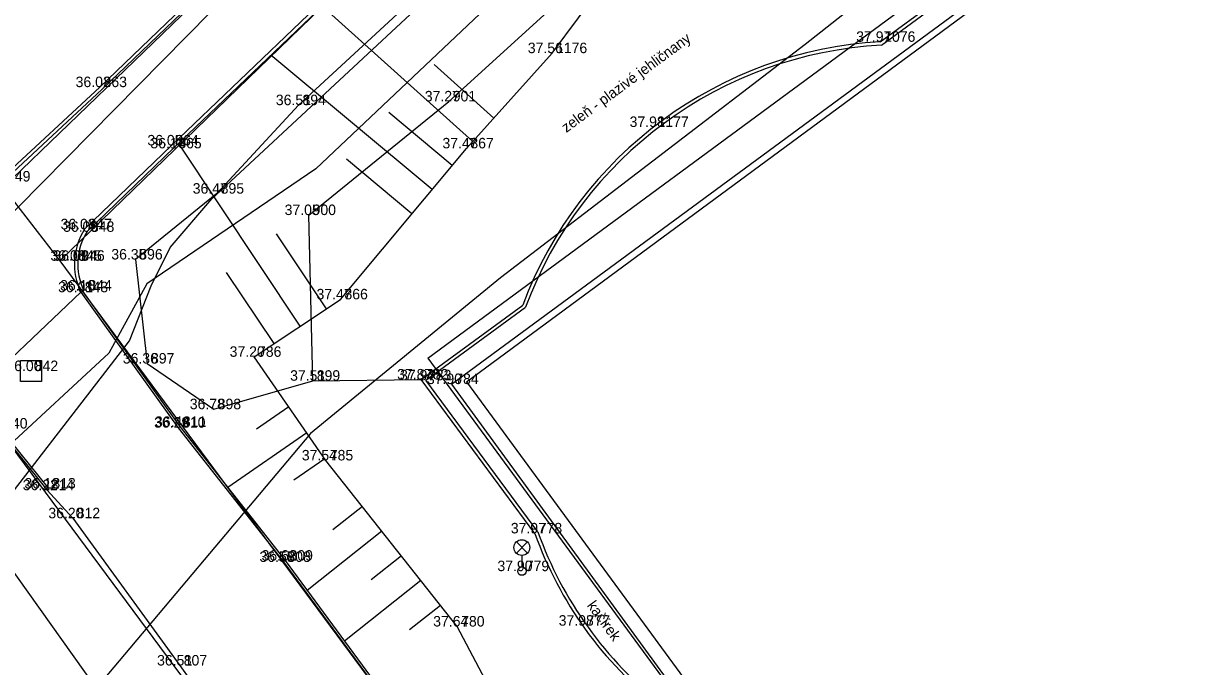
# Model space of a CAD drawing. Extents: x -609709 to -609357, y -1051535 to -1051131.
# Drawn here: x -609623.05 to -609595.44, y -1051283.31 to -1051267.96 of the extents above; entities that cross this region are included whole.
import ezdxf

# ---------------------------------------------------------------- set-up
doc = ezdxf.new("R2010")
doc.units = 0
for name, color, linetype in [('Vrstva 1', 7, 'Continuous'), ('Vrstva 10', 7, 'Continuous'), ('Vrstva 12', 7, 'Continuous'), ('Vrstva 15', 7, 'Continuous'), ('Vrstva 17', 7, 'Continuous'), ('Vrstva 2', 7, 'Continuous'), ('Vrstva 3', 7, 'Continuous'), ('Vrstva 4', 7, 'Continuous'), ('Vrstva 5', 7, 'Continuous'), ('Vrstva 6', 7, 'Continuous'), ('Vrstva 7', 7, 'Continuous'), ('Vrstva 8', 7, 'Continuous'), ('Vrstva 9', 7, 'Continuous')]:
    doc.layers.add(name, color=color, linetype=linetype)

msp = doc.modelspace()

# ---------------------------------------------------------------- linework, layer by layer
at = {"layer": 'Vrstva 1'}
for p, q in [((-609602.63, -1051268.41), (-609602.63, -1051268.41)), ((-609610.45, -1051268.68), (-609610.45, -1051268.68)), ((-609621.23, -1051269.49), (-609621.23, -1051269.49)), ((-609616.49, -1051269.92), (-609616.49, -1051269.92)), ((-609612.91, -1051269.83), (-609612.91, -1051269.83)), ((-609608.03, -1051270.44), (-609608.03, -1051270.44)), ((-609619.52, -1051270.88), (-609619.52, -1051270.88)), ((-609619.45, -1051270.95), (-609619.45, -1051270.95)), ((-609612.49, -1051270.95), (-609612.49, -1051270.95)), ((-609618.44, -1051272.03), (-609618.44, -1051272.03)), ((-609616.25, -1051272.54), (-609616.25, -1051272.54)), ((-609621.59, -1051272.88), (-609621.59, -1051272.88)), ((-609621.53, -1051272.94), (-609621.53, -1051272.94)), ((-609621.83, -1051273.63), (-609621.83, -1051273.63)), ((-609621.76, -1051273.63), (-609621.76, -1051273.63)), ((-609620.38, -1051273.6), (-609620.38, -1051273.6)), ((-609621.59, -1051274.34), (-609621.59, -1051274.34)), ((-609621.68, -1051274.38), (-609621.68, -1051274.38)), ((-609615.49, -1051274.55), (-609615.49, -1051274.55)), ((-609617.55, -1051275.92), (-609617.55, -1051275.92)), ((-609622.87, -1051276.26), (-609622.87, -1051276.26)), ((-609620.1, -1051276.08), (-609620.1, -1051276.08)), ((-609616.15, -1051276.49), (-609616.15, -1051276.49)), ((-609613.57, -1051276.46), (-609613.57, -1051276.46)), ((-609613.5, -1051276.48), (-609613.5, -1051276.48)), ((-609612.85, -1051276.57), (-609612.85, -1051276.57)), ((-609618.51, -1051277.17), (-609618.51, -1051277.17)), ((-609619.36, -1051277.61), (-609619.36, -1051277.61)), ((-609619.34, -1051277.59), (-609619.34, -1051277.59)), ((-609615.84, -1051278.39), (-609615.84, -1051278.39)), ((-609622.45, -1051279.06), (-609622.45, -1051279.06)), ((-609622.49, -1051279.1), (-609622.49, -1051279.1)), ((-609621.87, -1051279.77), (-609621.87, -1051279.77)), ((-609610.86, -1051280.13), (-609610.86, -1051280.13)), ((-609616.85, -1051280.81), (-609616.85, -1051280.81)), ((-609616.8, -1051280.78), (-609616.8, -1051280.78)), ((-609611.17, -1051281.03), (-609611.17, -1051281.03)), ((-609612.71, -1051282.35), (-609612.71, -1051282.35)), ((-609609.72, -1051282.33), (-609609.72, -1051282.33)), ((-609619.32, -1051283.28), (-609619.32, -1051283.28))]:
    msp.add_line(p, q, dxfattribs=at)
at = {"layer": 'Vrstva 10'}
for p, q in [((-609623.53, -1051271.88), (-609592.58, -1051242.01)), ((-609622.18, -1051273.63), (-609589.38, -1051241.83)), ((-609613.41, -1051275.95), (-609597.54, -1051264.25)), ((-609612.49, -1051276.52), (-609596.95, -1051265.05)), ((-609623.53, -1051271.88), (-609622.18, -1051273.63)), ((-609622.18, -1051273.63), (-609602.58, -1051300.13)), ((-609613.41, -1051275.95), (-609598.09, -1051296.84)), ((-609612.49, -1051276.52), (-609597.77, -1051296.6)), ((-609623.67, -1051277.61), (-609605.63, -1051301.94))]:
    msp.add_line(p, q, dxfattribs=at)
at = {"layer": 'Vrstva 12'}
for points in [[(-609644.336, -1051251.436), (-609604.801, -1051307.048), (-609620.698, -1051318.606), (-609619.426, -1051320.272)], [(-609598.88, -1051264.1), (-609604.42, -1051268.47), (-609611.68, -1051274.04), (-609616.21, -1051277.75), (-609621.57, -1051284.12), (-609621.25, -1051285.42), (-609619.8, -1051287.45), (-609615.97, -1051291.57), (-609612.96, -1051295.31), (-609611.54, -1051298.14), (-609609.99, -1051301.94), (-609609.26, -1051303.04), (-609608.61, -1051303.76)]]:
    msp.add_lwpolyline(points, dxfattribs=at)
at = {"layer": 'Vrstva 15'}
for points in [[(-609592.54, -1051249), (-609597.09, -1051253.54), (-609603.86, -1051260.31), (-609608.84, -1051264.59), (-609616.08, -1051271.44), (-609620.11, -1051274.18), (-609621.01, -1051275.83), (-609623.48, -1051278.12), (-609624.89, -1051278.61), (-609626.41, -1051281.76), (-609625.78, -1051282.81), (-609616.94, -1051293.56), (-609613.57, -1051297.39), (-609614.852, -1051298.693)], [(-609615.07, -1051296.33), (-609615.78, -1051295.09), (-609620.45, -1051288.93), (-609623.66, -1051284.97), (-609624.82, -1051283.57), (-609624.94, -1051283.19), (-609624.89, -1051282.73), (-609624.27, -1051280.91), (-609623.86, -1051279.98), (-609623.26, -1051279.09), (-609620.52, -1051275.54), (-609620, -1051274.23), (-609619.55, -1051273.31), (-609618.56, -1051272.15), (-609610.34, -1051264.5)]]:
    msp.add_lwpolyline(points, dxfattribs=at)
at = {"layer": 'Vrstva 17'}
msp.add_lwpolyline([(-609531.786, -1051180.515), (-609532.61, -1051181.07), (-609528.54, -1051185.58), (-609545.95, -1051201.69), (-609546.72, -1051202.27), (-609551.04, -1051206.15), (-609565.42, -1051219.63), (-609579.77, -1051233.3), (-609583.56, -1051235.84), (-609591.75, -1051241.92), (-609609.05, -1051258.52), (-609618.01, -1051267.11), (-609626.05, -1051275.26), (-609630.23, -1051279.58), (-609635.78, -1051285.7), (-609642.85, -1051291.4), (-609672.95, -1051307.23)], dxfattribs=at)
at = {"layer": 'Vrstva 4'}
for p, q in [((-609602.602, -1051268.489), (-609598.603, -1051265.555)), ((-609617.947, -1051266.442), (-609621.175, -1051269.548)), ((-609621.229, -1051269.489), (-609623.519, -1051271.62)), ((-609610.789, -1051280.092), (-609613.458, -1051276.477)), ((-609623.638, -1051277.663), (-609622.489, -1051279.091))]:
    msp.add_line(p, q, dxfattribs=at)
for points in [[(-609601.06, -1051253.08), (-609604.02, -1051255.96), (-609607.62, -1051259.41), (-609610.87, -1051262.54), (-609616.26, -1051267.77), (-609619.52, -1051270.88), (-609621.59, -1051272.88)], [(-609601.004, -1051253.137), (-609603.964, -1051256.018), (-609607.565, -1051259.468), (-609610.814, -1051262.598), (-609616.205, -1051267.828), (-609619.465, -1051270.938), (-609621.528, -1051272.931)], [(-609602.63, -1051268.41), (-609598.65, -1051265.49), (-609596.65, -1051264.02), (-609592.713, -1051261.096)], [(-609618.06, -1051266.44), (-609621.23, -1051269.49)], [(-609621.175, -1051269.548), (-609623.53, -1051271.74)], [(-609621.68, -1051274.38), (-609621.611, -1051274.339)], [(-609621.637, -1051274.354), (-609619.32, -1051277.58), (-609616.81, -1051280.78), (-609610.823, -1051288.92)], [(-609621.68, -1051274.38), (-609624.49, -1051277.05)], [(-609621.68, -1051274.38), (-609619.36, -1051277.61), (-609616.85, -1051280.81), (-609610.863, -1051288.949)], [(-609613.57, -1051276.46), (-609611.149, -1051274.688)], [(-609613.458, -1051276.477), (-609611.083, -1051274.738)], [(-609610.86, -1051280.13), (-609613.57, -1051276.46)], [(-609623.6, -1051277.63), (-609622.45, -1051279.06)], [(-609622.489, -1051279.091), (-609622.45, -1051279.06)], [(-609622.489, -1051279.091), (-609621.87, -1051279.77), (-609619.32, -1051283.28), (-609616.512, -1051287.217)]]:
    msp.add_lwpolyline(points, dxfattribs=at)
for centre, radius, start, end in [((-609602.075, -1051278.082), 9.688, 93.2811, 159.4889), ((-609602.075, -1051278.082), 9.608, 93.1402, 159.6312), ((-609620.285, -1051273.711), 1.547, 147.5118, 205.621), ((-609620.285, -1051273.711), 1.467, 147.8766, 205.3494), ((-609602.176, -1051277.026), 9.222, 199.6719, 231.8723), ((-609602.176, -1051277.026), 9.142, 199.5981, 231.9379)]:
    msp.add_arc(centre, radius, start, end, dxfattribs=at)
at = {"layer": 'Vrstva 5'}
for p, q in [((-609611.302, -1051280.6), (-609611.037, -1051280.335)), ((-609611.302, -1051280.335), (-609611.037, -1051280.6)), ((-609611.17, -1051280.655), (-609611.17, -1051280.93))]:
    msp.add_line(p, q, dxfattribs=at)
msp.add_lwpolyline([(-609623.12, -1051276.01), (-609622.62, -1051276.01), (-609622.62, -1051276.51), (-609623.12, -1051276.51)], close=True, dxfattribs=at)
for centre, radius in [((-609611.17, -1051280.468), 0.188), ((-609611.17, -1051281.03), 0.1)]:
    msp.add_circle(centre, radius, dxfattribs=at)
at = {"layer": 'Vrstva 6'}
msp.add_lwpolyline([(-609610.31, -1051288.53), (-609610.4, -1051286.73), (-609612.71, -1051282.35), (-609615.84, -1051278.39), (-609617.55, -1051275.92), (-609615.49, -1051274.55), (-609612.49, -1051270.95), (-609610.45, -1051268.68), (-609607.94, -1051265.3), (-609606.28, -1051264.06), (-609602.59, -1051259.95), (-609593.93, -1051248.07), (-609590.64, -1051244.54), (-609589.23, -1051241.892)], dxfattribs=at)
at = {"layer": 'Vrstva 7'}
for points in [[(-609602.81, -1051256.87), (-609609.78, -1051263.4), (-609613.32, -1051266.99), (-609616.49, -1051269.92), (-609618.44, -1051272.03), (-609620.38, -1051273.6), (-609620.1, -1051276.08), (-609618.51, -1051277.17), (-609616.15, -1051276.49)], [(-609612.91, -1051269.83), (-609607.94, -1051265.3), (-609602.48, -1051262.57), (-609602.59, -1051259.95), (-609600.81, -1051258.44), (-609602.81, -1051256.87)], [(-609616.15, -1051276.49), (-609616.25, -1051272.54), (-609612.91, -1051269.83)], [(-609616.15, -1051276.49), (-609613.57, -1051276.46)]]:
    msp.add_lwpolyline(points, dxfattribs=at)
at = {"layer": 'Vrstva 8'}
for p, q in [((-609612.342, -1051270.786), (-609615.93, -1051267.561)), ((-609613.309, -1051271.933), (-609617.151, -1051268.731)), ((-609611.841, -1051270.228), (-609613.261, -1051268.952)), ((-609612.829, -1051271.356), (-609614.339, -1051270.098)), ((-609616.452, -1051275.19), (-609619.351, -1051270.83)), ((-609613.789, -1051272.509), (-609615.352, -1051271.206)), ((-609615.827, -1051274.774), (-609617.016, -1051272.986)), ((-609617.076, -1051275.605), (-609618.206, -1051273.906)), ((-609616.722, -1051277.115), (-609617.49, -1051277.647)), ((-609616.296, -1051277.732), (-609618.178, -1051279.035)), ((-609615.869, -1051278.349), (-609616.607, -1051278.86)), ((-609614.969, -1051279.492), (-609615.674, -1051280.049)), ((-609614.504, -1051280.08), (-609616.288, -1051281.49)), ((-609614.039, -1051280.669), (-609614.76, -1051281.239)), ((-609613.574, -1051281.257), (-609615.398, -1051282.699)), ((-609613.109, -1051281.846), (-609613.847, -1051282.429))]:
    msp.add_line(p, q, dxfattribs=at)
at = {"layer": 'Vrstva 9'}
for points in [[(-609612.85, -1051276.57), (-609594.51, -1051263.06)], [(-609612.85, -1051276.57), (-609606.19, -1051285.7)]]:
    msp.add_lwpolyline(points, dxfattribs=at)

# ---------------------------------------------------------------- texts
at = {"layer": 'Vrstva 2'}
for s, p in [(' 1076', (-609602.63, -1051268.41)), (' 1176', (-609610.45, -1051268.68)), (' 863', (-609621.23, -1051269.49)), (' 894', (-609616.49, -1051269.92)), (' 901', (-609612.91, -1051269.83)), (' 1177', (-609608.03, -1051270.44)), (' 864', (-609619.52, -1051270.88)), (' 865', (-609619.45, -1051270.95)), (' 867', (-609612.49, -1051270.95)), (' 849', (-609623.53, -1051271.74)), (' 895', (-609618.44, -1051272.03)), (' 900', (-609616.25, -1051272.54)), (' 847', (-609621.59, -1051272.88)), (' 848', (-609621.53, -1051272.94)), (' 845', (-609621.83, -1051273.63)), (' 846', (-609621.76, -1051273.63)), (' 896', (-609620.38, -1051273.6)), (' 844', (-609621.59, -1051274.34)), (' 843', (-609621.68, -1051274.38)), (' 866', (-609615.49, -1051274.55)), (' 786', (-609617.55, -1051275.92)), (' 842', (-609622.87, -1051276.26)), (' 897', (-609620.1, -1051276.08)), (' 899', (-609616.15, -1051276.49)), (' 782', (-609613.57, -1051276.46)), (' 783', (-609613.5, -1051276.48)), (' 784', (-609612.85, -1051276.57)), (' 898', (-609618.51, -1051277.17)), (' 840', (-609623.6, -1051277.63)), (' 810', (-609619.36, -1051277.61)), (' 811', (-609619.34, -1051277.59)), (' 785', (-609615.84, -1051278.39)), (' 814', (-609622.49, -1051279.1)), (' 813', (-609622.45, -1051279.06)), (' 812', (-609621.87, -1051279.77)), (' 778', (-609610.86, -1051280.13)), (' 808', (-609616.85, -1051280.81)), (' 809', (-609616.8, -1051280.78)), (' 779', (-609611.17, -1051281.03)), (' 780', (-609612.71, -1051282.35)), (' 777', (-609609.72, -1051282.33)), (' 807', (-609619.32, -1051283.28))]:
    msp.add_text(s, height=0.25, dxfattribs=at).set_placement(p)
at = {"layer": 'Vrstva 3'}
for s, p in [('37.97', (-609603.203, -1051268.41)), ('37.56', (-609611.029, -1051268.68)), ('36.02', (-609621.803, -1051269.49)), ('36.51', (-609617.032, -1051269.92)), ('37.27', (-609613.483, -1051269.83)), ('37.98', (-609608.603, -1051270.44)), ('36.05', (-609620.093, -1051270.88)), ('36.14', (-609620.023, -1051270.95)), ('37.47', (-609613.063, -1051270.95)), ('36.47', (-609619.013, -1051272.03)), ('37.05', (-609616.823, -1051272.54)), ('36.03', (-609622.163, -1051272.88)), ('36.09', (-609622.103, -1051272.94)), ('36.03', (-609622.403, -1051273.63)), ('36.09', (-609622.333, -1051273.63)), ('36.35', (-609620.953, -1051273.6)), ('36.10', (-609622.173, -1051274.34)), ('36.01', (-609622.222, -1051274.38)), ('37.47', (-609616.063, -1051274.55)), ('37.20', (-609618.133, -1051275.92)), ('36.00', (-609623.453, -1051276.26)), ('36.36', (-609620.679, -1051276.08)), ('37.51', (-609616.692, -1051276.49)), ('37.87', (-609614.143, -1051276.46)), ('37.97', (-609614.073, -1051276.48)), ('37.90', (-609613.433, -1051276.57)), ('36.78', (-609619.083, -1051277.17)), ('36.29', (-609619.933, -1051277.61)), ('36.44', (-609619.913, -1051277.59)), ('37.54', (-609616.413, -1051278.39)), ('36.22', (-609623.063, -1051279.1)), ('36.12', (-609623.023, -1051279.06)), ('36.20', (-609622.453, -1051279.77)), ('37.97', (-609611.433, -1051280.13)), ('36.55', (-609617.423, -1051280.81)), ('36.62', (-609617.373, -1051280.78)), ('37.90', (-609611.753, -1051281.03)), ('37.64', (-609613.283, -1051282.35)), ('37.98', (-609610.293, -1051282.33)), ('36.51', (-609619.862, -1051283.28))]:
    msp.add_text(s, height=0.25, dxfattribs=at).set_placement(p)
at = {"layer": 'Vrstva 5'}
msp.add_text('kačírek', height=0.25, rotation=306.1235, dxfattribs=at).set_placement((-609609.629, -1051281.85))
at = {"layer": 'Vrstva 7'}
msp.add_text('zeleň - plazivé jehličnany', height=0.25, rotation=36.3991, dxfattribs=at).set_placement((-609610.111, -1051270.585))

doc.saveas('drawing.dxf')
